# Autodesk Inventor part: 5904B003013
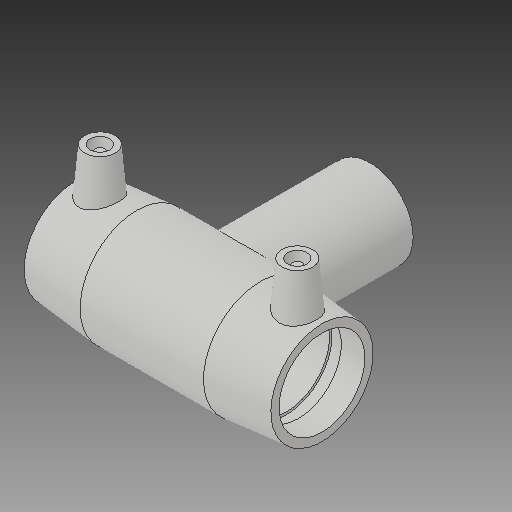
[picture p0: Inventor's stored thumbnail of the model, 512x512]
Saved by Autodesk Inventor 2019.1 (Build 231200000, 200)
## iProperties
Created: 2017-06
Part Number: 5904B003013
Material: Generic
Description: PLASSON TEE 1 1/4''IPS
Document SubType Name: Modeling
Designer: KIM
Mass: 17327.5 g
Surface Area: 12195.1 cm^2
Volume: 17327.5 cm^3
Density: 1 g/cm^3
Appearance: Default
Author: KIM
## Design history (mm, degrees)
derived "5904B.ipt"
feature "Solid1::5904B.ipt"
tag "TaggingFeature1"
body "Solid1"
other parameters: "d0" = 120.904, "d1" = 42.1, "d2" = 55.626, "d3" = 43.434, "d4" = 30.226, "d5" = 50.0634, "d6" = 39.995, "d7" = 42.1, "d8" = 168 deg, "d10" = 17.3736, "d11" = 5.7912, "d13" = 120.904, "d14" = 17.6296, "d17" = 37.89, "d18" = 42.1, "d19" = 3.52592, "d20" = 168 deg, "d22" = 51.73218, "d23" = 55.626, "d24" = 50.18021, "d25" = 135 deg, "d26" = 84.6328, "d27" = 135 deg, "d29" = 46.736, "d30" = 15, "d31" = 48.3616, "d34" = 5 deg, "d35" = 15, "d39" = 5 deg, "d40" = 9.6, "d41" = 4.8, "d42" = 6, "d43" = 0, "d45" = 4, "d46" = 14, "d47" = 0, "d48" = -84.074, "d49" = 42.1, "d51" = 0, "d52" = 33.68, "d54" = 0, "d55" = 50.0634, "d56" = 55.626, "d57" = 42.3164, "d58" = 135 deg, "d59" = 43.434, "d60" = 43.434, "d61" = 135 deg, "d62" = 84.074, "d72" = 55.01132, "d73" = 27.50566, "d74" = -84.074, "d75" = 44.205, "d77" = 0, "d78" = 33.68, "d80" = 0, "d81" = 42.1, "d82" = 56.261, "d83" = 0, "d84" = 3, "d85" = 0, "d86" = 3, "d87" = 0, "d88" = 12.59586, "d89" = 3.14896, "d90" = 12.59586, "d_" = 42.1, "L_" = 120.904, "L_1" = 43.434, "D_" = 55.626, "A_" = 46.736, "d_2" = 12, "H_" = 84.074
